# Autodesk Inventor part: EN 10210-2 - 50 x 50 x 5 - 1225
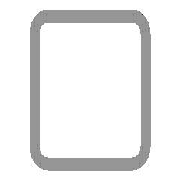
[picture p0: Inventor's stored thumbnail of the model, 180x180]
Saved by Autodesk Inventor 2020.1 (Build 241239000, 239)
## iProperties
IsCustomPart: 1
_CCFamilyMember: 16
_CCFamilyDisplayName: DIN EN 10210-2 (USAS B17.1 quadratisch) - Rohrleitung — In Klammern angegebene Größen wurden aufgehoben
_FrameMemberDoc: Frame Member File
_Version: 15.0.0
_GetPNFromCC: 1
Created: 2019-01
Part Number: EN 10210-2 - 50 x 50 x 5 - 1225
Material: Stahl, weich
Description: Rohrleitung
Document SubType Name: Modeling
Standard: DIN
Designer: lutzd
Standard Revision: 2006-07
Standards Organization: DIN
Language: de-DE
Size Designation: 50 x 50 x 5
Categories: <MemberInstance><Categories><Category DisplayName="Profile" InternalName="089c4875-fa83-4c05-b084-43b9cc11f5ed" Mnemonic="GRDR"><CategoryParameter DisplayName="
Stock Number: 50 x 50 x 5
Mass: 8392.58 g
Surface Area: 4165.63 cm^2
Volume: 1069.12 cm^3
Density: 7.85 g/cm^3
Appearance: Halbpoliert
G_L: 1225,000 mm
G_W: 50,000 mm
G_H: 50,000 mm
Dimensions: 50x50x1225 mm
Mass: 8,393 kg
DocNumber: ADSK-014091
Folder: .
+F718B410-1E83-4FED-9613-71FDBF8476AF+SCHNITTDETAIL1: Schnittwinkel 90,00 grd
+3E72B3EB-1A68-4ADB-AFD6-9EB54AA26196+SCHNITTDETAIL2: Schnittwinkel 90,00 grd
Title: Profil-Bauteil
Author: lutzd
Revision Number: -
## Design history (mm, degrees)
node "Startebene"
node "Endebene"
sketch "Skizze"
  geometry: L1 (-25, -17.5)-(-25, 17.5); L2 (-17.5, 25)-(17.5, 25); L3 (25, 17.5)-(25, -17.5); L4 (17.5, -25)-(-17.5, -25); L5 (-15, 20)-(15, 20); L6 (20, 15)-(20, -15); L7 (15, -20)-(-15, -20); L8 (-20, -15)-(-20, 15); L9 (0, 37.175)-(0, -37.175) reference; L10 (-37.175, 0)-(37.175, 0) reference; A1 r 7.5 centre (-17.5, -17.5) between (-25, -17.5) and (-17.5, -25); A2 r 7.5 centre (-17.5, 17.5) between (-17.5, 25) and (-25, 17.5); A3 r 7.5 centre (17.5, 17.5) between (25, 17.5) and (17.5, 25); A4 r 7.5 centre (17.5, -17.5) between (17.5, -25) and (25, -17.5); A5 r 5 centre (-15, -15) between (-20, -15) and (-15, -20); A6 r 5 centre (-15, 15) between (-15, 20) and (-20, 15); A7 r 5 centre (15, 15) between (20, 15) and (15, 20); A8 r 5 centre (15, -15) between (15, -20) and (20, -15)
  constraints: 16 end point, 16 point on circle, 16 tangent, 8 centre point, 6 equal radius, 4 parallel, 2 perpendicular, 2 other
  dimensions: "d7" = 7.5 radius of A1 (= G_IR); "d10" = 50 distance between parallel lines of L2 L4 (= G_H); "d11" = 50 distance between parallel lines of L1 L3 (= G_W); "d12" = 5 distance between parallel lines of L3 L6 (= G_T); "d15" = 25 distance between parallel lines of L2 L10 (= 0.5 x d10); "d16" = 25 distance between parallel lines of L9 L3 (= 0.5 x d11); "d19" = 5 radius of A5 (= G_T); "d20" = 5 distance between parallel lines of L4 L7 (= G_T)
extrude "Körper" new body sketch "Skizze" stored distance "d3" = 1225 (= G_L); taper "d4" = 0 deg
node "Driven Length"
  sketch "Sketch3"
    geometry: L1 (0, 0)-(10, 0) reference
    constraints: 2 end point, 1 horizontal
  workplane "Work Plane3"
  sketch "Sketch4"
    geometry: L1 (-2, 50)-(12, 50) reference; L2 (-2, 1275)-(12, 1275) reference
    dimensions: "d18" = 1225 distance between parallel lines of L1 L2 (derived)
workplane "Arbeitsebene4"
feature "Trennen1"
workplane "Arbeitsebene5"
feature "Trennen2"
sketch "Skizze5"
  geometry: L1 (-35, 1225)-(0, 1225) reference; L2 (-17.5, 1225)-(-17.5, 626); 4 further points
  constraints: 2 end point, 2 point on line, 1 coincident, 1 midpoint, 1 vertical
  dimensions: "d21" = 115 distance of point (-17.5, 741) point (-17.5, 856); "d22" = 115 distance of point (-17.5, 741) point (-17.5, 626) (= d21); "d23" = 369 distance from line of point (-17.5, 856) L1
hole "Bohrung1" sketch "Skizze5" at (-17.5, 626), (-17.5, 741), (-17.5, 856) diameter "d24" = 6.647; stored, may be unused: countersink angle "d28" = 90 deg, drill point angle "d30" = 118 deg; dims "d25" = 16, "d26" = 4, "d27" = 2, "d29" = 8
body "Solid1"
other parameters: "G_W" = 50 [user parameter; used in 1 equation term], "G_H" = 50 [user parameter; used in 1 equation term], "G_T" = 5 [user parameter; used in 3 equation terms], "G_IR" = 7.5 [user parameter; used in 1 equation term], "G_L" = 1225 (= d18) [user parameter; used in 1 equation term], "G_OFFSET_END" = -25 [user parameter; used in 1 equation term], "d14" = 1275 (= G_OFFSET_END + B_L), "d17" = 90 deg
